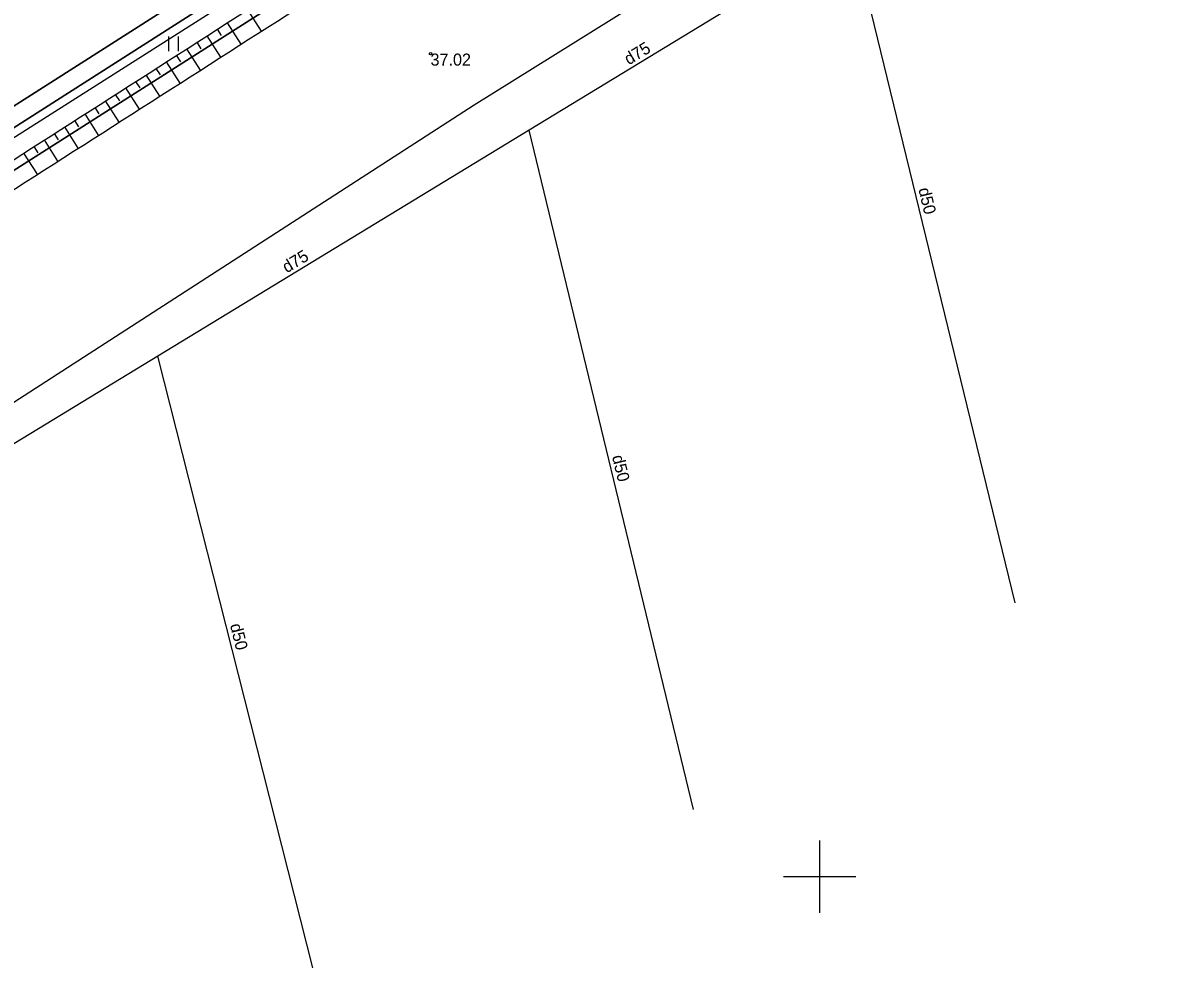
# Model space of a CAD drawing. Extents: x 469981 to 472086, y 246785 to 247785.
# Drawn here: x 471567.02 to 471613.93, y 247446.58 to 247485.33 of the extents above; entities that cross this region are included whole.
import ezdxf

# ---------------------------------------------------------------- set-up
doc = ezdxf.new("R2010")
doc.units = 0
for name, color, linetype in [('0_Asfalta_mala', 7, 'Continuous'), ('0_Asfalta_Nomale', 7, 'Continuous'), ('0_Ruut_Braukt', 7, 'Continuous'), ('0_Ruut_nomale', 7, 'Continuous'), ('CELI_CMAL_####_####_#', 7, 'Continuous'), ('DREN_VADP_####_####_#', 7, 'Continuous'), ('DREN_VADP_####_TKST_#', 7, 'Continuous'), ('DREN_VADP_KLKT_####_#', 7, 'Continuous'), ('DREN_VADP_KLKT_TKST_#', 7, 'Continuous'), ('GEOD_ELEM_####_####_#', 7, 'Continuous'), ('RAMI_UZMR_####_####_#', 7, 'Continuous'), ('RELJ_AATZ_####_TKST_#', 7, 'Continuous'), ('RELJ_ELEM_####_####_#', 7, 'Continuous'), ('RELJ_NOGA_####_####_#', 7, 'Continuous'), ('RELJ_NOGL_####_####_#', 7, 'Continuous'), ('ROBZ_IERR_####_####_#', 7, 'Continuous'), ('ROBZ_PROJ_####_####_#', 7, 'Continuous'), ('TERT_ELEM_####_####_#', 7, 'Continuous')]:
    doc.layers.add(name, color=color, linetype=linetype)

msp = doc.modelspace()

# ---------------------------------------------------------------- linework, layer by layer
at = {"layer": '0_Asfalta_mala'}
msp.add_line((471712.743, 247575.147), (471339.517, 247336.876), dxfattribs=at)
at = {"layer": '0_Asfalta_Nomale'}
msp.add_line((471695.558, 247563.285), (471399.037, 247373.985), dxfattribs=at)
at = {"layer": '0_Ruut_Braukt'}
msp.add_line((471339.517, 247336.876), (471712.743, 247575.147), dxfattribs=at)
at = {"layer": '0_Ruut_nomale'}
for p, q in [((471712.743, 247575.147), (471514.049, 247448.299)), ((471514.294, 247447.566), (471695.558, 247563.285))]:
    msp.add_line(p, q, dxfattribs=at)
at = {"layer": 'CELI_CMAL_####_####_#'}
msp.add_lwpolyline([(471449.387, 247405.104), (471473.787, 247420.91), (471502.643, 247439.527), (471533.217, 247459.11), (471556.347, 247474.048), (471582.788, 247490.845), (471613.475, 247511.118), (471642.713, 247530.159), (471668.616, 247547.038), (471690.82, 247561.728), (471696.388, 247565.088), (471697.928, 247564.145), (471698.695, 247563.022), (471698.327, 247552.674), (471698.209, 247547.7)], dxfattribs=at)
at = {"layer": 'DREN_VADP_####_####_#'}
for points in [[(471608.097, 247461.322), (471601.35, 247489.016)], [(471594.778, 247452.782), (471587.985, 247480.886)], [(471579.803, 247443.18), (471572.618, 247471.538)]]:
    msp.add_lwpolyline(points, dxfattribs=at)
at = {"layer": 'DREN_VADP_KLKT_####_#'}
for points in [[(471874.265, 247606.401), (471874.259, 247606.399), (471867.456, 247605.226), (471862.705, 247604.407), (471853.259, 247602.776), (471834.413, 247599.524), (471815.19, 247596.208), (471796.375, 247592.962), (471778.135, 247589.816), (471762.691, 247587.151), (471760.751, 247585.97), (471739.894, 247573.284), (471721.842, 247562.305), (471686.843, 247541.016), (471672.454, 247532.264), (471658.683, 247523.887), (471644.34, 247515.163), (471630.529, 247506.762), (471615.384, 247497.552), (471601.35, 247489.016), (471587.985, 247480.886)], [(471587.985, 247480.886), (471572.618, 247471.538), (471557.965, 247462.626), (471543.948, 247454.101), (471528.621, 247444.777), (471514.071, 247435.928), (471499.173, 247426.865), (471484.028, 247417.654), (471469.828, 247409.016), (471455.954, 247400.578)]]:
    msp.add_lwpolyline(points, dxfattribs=at)
at = {"layer": 'GEOD_ELEM_####_####_#'}
for p, q in [((471600, 247451.5), (471600, 247450)), ((471598.5, 247450), (471600, 247450)), ((471600, 247450), (471600, 247448.5)), ((471600, 247450), (471601.5, 247450))]:
    msp.add_line(p, q, dxfattribs=at)
at = {"layer": 'RAMI_UZMR_####_####_#'}
msp.add_lwpolyline([(471848.639, 247612.324), (471820.308, 247604.26), (471796.252, 247602.503), (471771.845, 247596.352), (471738.658, 247580.538), (471704.768, 247555.586), (471706.876, 247550.666), (471698.447, 247548.03), (471696.867, 247547.678), (471692.126, 247547.503), (471681.941, 247541.88), (471585.706, 247481.922), (471472.95, 247409.108), (471442.347, 247392.641), (471399.385, 247364.445), (471380.292, 247353.371), (471352.036, 247335.759)], dxfattribs=at)
at = {"layer": 'RELJ_ELEM_####_####_#'}
msp.add_circle((471583.898, 247484.054), 0.05, dxfattribs=at)
at = {"layer": 'RELJ_NOGA_####_####_#'}
for p, q in [((471576.326, 247485.87), (471576.894, 247484.985)), ((471575.484, 247485.33), (471576.051, 247484.446)), ((471574.642, 247484.791), (471575.208, 247483.907)), ((471575.063, 247485.06), (471575.233, 247484.795)), ((471574.221, 247484.521), (471574.391, 247484.256)), ((471573.379, 247483.982), (471573.548, 247483.717)), ((471573.8, 247484.251), (471574.365, 247483.369)), ((471572.537, 247483.443), (471572.706, 247483.178)), ((471572.958, 247483.712), (471573.522, 247482.83)), ((471572.116, 247483.173), (471572.68, 247482.292)), ((471571.273, 247482.634), (471571.837, 247481.753)), ((471571.694, 247482.904), (471571.864, 247482.639)), ((471570.431, 247482.096), (471570.994, 247481.215)), ((471570.852, 247482.365), (471571.021, 247482.101)), ((471569.588, 247481.557), (471570.151, 247480.676)), ((471570.01, 247481.826), (471570.179, 247481.562)), ((471569.167, 247481.287), (471569.336, 247481.023)), ((471568.325, 247480.749), (471568.494, 247480.485)), ((471568.746, 247481.018), (471569.309, 247480.138)), ((471567.482, 247480.21), (471567.651, 247479.946)), ((471567.904, 247480.479), (471568.466, 247479.6)), ((471567.061, 247479.94), (471567.624, 247479.061))]:
    msp.add_line(p, q, dxfattribs=at)
for points in [[(471341.934, 247360.736), (471344.51, 247356.259), (471349.946, 247353.745), (471355.895, 247354.991), (471376.693, 247368.011), (471396.058, 247380.323), (471444.047, 247411.052), (471471.484, 247428.432), (471497.591, 247445.096), (471529.061, 247465.658), (471552.024, 247480.39), (471579.849, 247498.336), (471608.29, 247516.955), (471640.013, 247537.434), (471663.526, 247552.835), (471700.309, 247577.155), (471731.58, 247596.998), (471755.893, 247610.638), (471758.96, 247612.207)], [(471398.635, 247372.113), (471402.433, 247374.78), (471425.587, 247389.134), (471450.058, 247404.807), (471474.143, 247419.972), (471503.215, 247438.678), (471533.565, 247458.24), (471556.869, 247473.387), (471582.759, 247490.013), (471614.043, 247510.505), (471643.167, 247529.241), (471669.12, 247546.6), (471690.757, 247560.622), (471694.708, 247563.158)]]:
    msp.add_spline(points, degree=3, dxfattribs=at)
at = {"layer": 'RELJ_NOGL_####_####_#'}
for points in [[(471342.514, 247361.025), (471345.404, 247356.891), (471350.224, 247354.862), (471355.251, 247356.423), (471376.007, 247368.362), (471395.596, 247380.988), (471443.663, 247411.567), (471471.284, 247429.247), (471497.369, 247445.866), (471528.273, 247466.831), (471551.61, 247481.241), (471579.417, 247499.099), (471607.686, 247517.412), (471639.588, 247538.317), (471662.844, 247553.564), (471699.582, 247577.982), (471731.348, 247598.063), (471755.711, 247611.433), (471758.267, 247612.728)], [(471399.82, 247371.525), (471403.248, 247373.923), (471426.144, 247388.265), (471450.973, 247403.909), (471474.455, 247419.142), (471503.701, 247437.899), (471533.875, 247457.475), (471557.479, 247472.578), (471583.176, 247489.002), (471614.915, 247509.524), (471643.61, 247528.29), (471669.945, 247545.695), (471691.536, 247559.696), (471695.147, 247562.053)]]:
    msp.add_spline(points, degree=3, dxfattribs=at)
at = {"layer": 'ROBZ_IERR_####_####_#'}
msp.add_lwpolyline([(471433.786, 247309.121), (471398.351, 247372.094), (471700.012, 247564.123), (471698.286, 247462.937)], dxfattribs=at)
at = {"layer": 'ROBZ_PROJ_####_####_#'}
msp.add_lwpolyline([(471341.261, 247348.2), (471524.883, 247464.852), (471765.831, 247617.357), (471863.461, 247637.05), (471867.531, 247625.725), (471827.071, 247615.935), (471808.63, 247612.294), (471769.199, 247605.751), (471757.886, 247600.963), (471700.012, 247564.123), (471398.351, 247372.094), (471346.741, 247338.478)], dxfattribs=at)
at = {"layer": 'TERT_ELEM_####_####_#'}
for p, q in [((471573.064, 247484.158), (471573.064, 247484.758)), ((471573.464, 247484.158), (471573.464, 247484.758))]:
    msp.add_line(p, q, dxfattribs=at)

# ---------------------------------------------------------------- texts
at = {"layer": 'DREN_VADP_####_TKST_#'}
for rotation, p in [(283.692, (471604.08, 247478.444)), (283.5889, (471591.403, 247467.382)), (284.2169, (471575.593, 247460.408))]:
    msp.add_text('d50', height=0.5, rotation=rotation, dxfattribs=at).set_placement(p)
at = {"layer": 'DREN_VADP_KLKT_TKST_#'}
for rotation, p in [(31.3123, (471592.102, 247483.565)), (31.3106, (471577.953, 247474.959))]:
    msp.add_text('d75', height=0.5, rotation=rotation, dxfattribs=at).set_placement(p)
at = {"layer": 'RELJ_AATZ_####_TKST_#'}
msp.add_text('37.02', height=0.5, dxfattribs=at).set_placement((471583.898, 247483.554))

doc.saveas('drawing.dxf')
